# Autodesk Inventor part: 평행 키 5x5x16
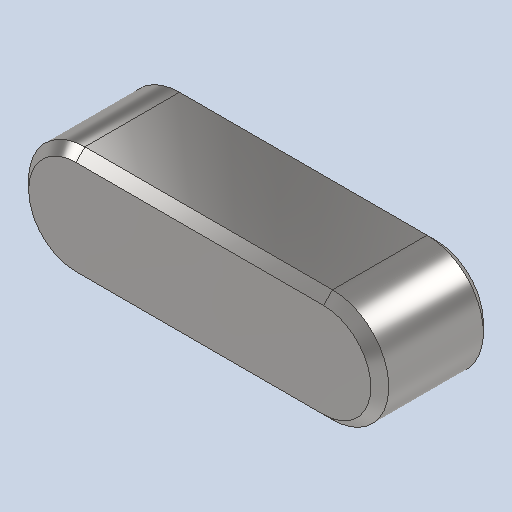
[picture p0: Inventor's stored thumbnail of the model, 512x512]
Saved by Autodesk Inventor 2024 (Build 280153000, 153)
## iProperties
Created: 2026-01
Part Number: 평행 키 5x5x16
Material: 강철, 연강
Description: 키 및 해당 키홈
Document SubType Name: Modeling
Designer: 2-10
Density: 7.85 g/cm^3
Appearance: 기본값
Author: jhkim
Sending System: Autodesk Inventor 2026
Preprocessor: ST-DEVELOPER v20.1
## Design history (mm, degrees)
node "평행 키 5x5x161"
node "솔리드1"
body "Solid1"
